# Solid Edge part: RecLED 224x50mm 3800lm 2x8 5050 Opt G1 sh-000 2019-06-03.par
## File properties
Author: sylwester.cabaj
Template: iso metric part.par
Last saved by: sylwester.cabaj
Revision: 2
Application: Solid Edge
Gęstość: 0,000 kg/m^3
Dokładność: 0,990
Username: sylwester.cabaj
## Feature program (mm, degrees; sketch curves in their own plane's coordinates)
body "unnamed Body 1"
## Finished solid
Body 1: solid body, 541 faces, 1367 edges, 829 vertices.
  Faces by surface: plane 277, cylinder 130, spline 80, cone 26, torus 11, sphere 10, spun 7
  Edges by curve: line 796, curve on surface 282, circle 179, ellipse 66, spline 38, intersection 6
Bounding box of the edges (mm; curved faces can reach further): 49.500 x 4.950 x 223.000, from (-24.75, -3.45, -111.5) to (24.75, 1.5, 111.5).
Cylindrical faces by radius (mm): R0.2 x39, R0.2002 x2, R0.2169 x3, R0.25 x12, R0.3 x2, R0.3373 x3, R0.4 x8, R0.4006 x2, R0.4008 x2, R0.525 x2, R0.6 x12, R1 x7, R1.05 x16, R1.0894 x2, R1.1 x14, R1.75 x4
Conical faces (half-angle, radius in mm at the cone's reference point): 0.5 deg R0.5056 x4, 0.5 deg R1.0082 x4, 1 deg R0.5511 x2, 10 deg R0.2132 x2, 10 deg R0.4132 x2, 18.4844 deg R1.0657 x4, 27.363 deg R0.6214 x2, 45 deg R0.575 x2, 45 deg R0.625 x4
Toroidal faces (ring radius, tube radius in mm): R0.1 r0.2 x1, R0.8 r0.2 x4, R0.8522 r0.3 x2, R0.9002 r0.2 x1, R0.9018 r0.2 x1, R1.3 r0.2 x2
Spherical faces by radius (mm): R0.2 x8, R0.6 x2
Planar faces by outward normal: +x 29, +y 8, +z 25, -x 29, -y 52, -z 34, oblique 100
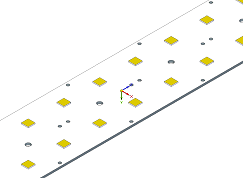
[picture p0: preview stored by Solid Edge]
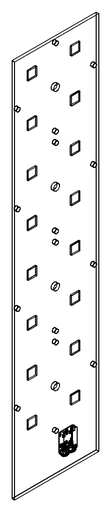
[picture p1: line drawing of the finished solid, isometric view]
